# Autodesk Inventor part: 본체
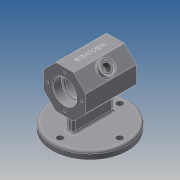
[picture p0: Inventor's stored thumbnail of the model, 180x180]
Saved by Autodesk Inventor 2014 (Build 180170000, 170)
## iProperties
Created: 2021-02
Part Number: 본체
Material: Generic
Document SubType Name: Modeling
Designer: kb542-20
Density: 1 g/cm^3
Appearance: Default
Author: kb542-20
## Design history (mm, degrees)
sketch "스케치1" dims "d0" = 58
  geometry: L1 (12.012, 29)-(29, 12.012); L2 (29, 12.012)-(29, -12.012); L3 (29, -12.012)-(12.012, -29); L4 (12.012, -29)-(-12.012, -29); L5 (-12.012, -29)-(-29, -12.012); L6 (-29, -12.012)-(-29, 12.012); L7 (-29, 12.012)-(-12.012, 29); L8 (-12.012, 29)-(12.012, 29); 5 further points
  constraints: 16 end point, 3 coincident, 1 horizontal, 1 midpoint, 1 vertical alignment, 19 other
extrude "돌출1" new body sketch "스케치1" stored distance "d1" = 70; taper "d2" = 0 deg
node "작업 평면1"
sketch "스케치3"
  geometry: C1 r 52 at (0, 0); C2 r 4.5 at (0, 41); C3 r 4.5 at (-41, 0); C4 r 4.5 at (0, -41); C5 r 4.5 at (41, 0); A1 r 41 centre (0, 0) between (0, 41) and (-41, 0); 1 further point
  constraints: 6 centre point, 4 point on circle, 3 equal radius, 2 coincident, 2 horizontal alignment, 2 vertical alignment
  dimensions: "d14" = 104 diameter of C1; "d15" = 82 diameter of A1; "d16" = 9 diameter of C2
extrude "돌출2" join sketch "스케치3" distance "d17" = 10; taper "d18" = 0 deg
sketch "스케치4"
  geometry: L1 (-5, 28)-(5, 28); L2 (5, 28)-(5, -28); L3 (5, -28)-(-5, -28); L4 (-5, -28)-(-5, 28); C1 r 52 at (0, 0) reference; 2 further points
  constraints: 8 end point, 2 midpoint, 2 parallel, 1 horizontal, 1 horizontal alignment, 1 perpendicular, 1 vertical alignment
  dimensions: "d19" = 56 distance of L1.end L2.end; "d20" = 10 distance of L1.start L1.end
extrude "돌출3" join sketch "스케치4" stored distance "d21" = 10; taper "d22" = 0 deg
sketch "스케치7"
  geometry: L1 (-35, 12.012)-(-35, -12.012) reference; L2 (-35, 0)-(0, 0); L3 (-35, 0)-(-35, 16); L4 (-35, 16)-(-23, 16); L5 (-23, 16)-(-23, 14); L6 (-23, 14)-(-20, 14); L7 (-20, 14)-(-20, 22); L8 (-20, 22)-(0, 22); L9 (0, 22)-(0, 0); L10 (35, 0)-(0, 0); L11 (35, 0)-(35, 16); L12 (35, 16)-(23, 16); L13 (23, 16)-(23, 14); L14 (23, 14)-(20, 14); L15 (20, 14)-(20, 22); L16 (20, 22)-(0, 22); 1 further point
  constraints: 30 end point, 7 symmetric about line, 5 parallel, 2 perpendicular, 1 midpoint
  dimensions: "d39" = 44 diameter of L16 L10; "d40" = 32 diameter of L4 L2; "d41" = 28 diameter of L6 L2; "d42" = 12 distance of L3.end L4.end; "d43" = 3 distance of L5.end L6.end
revolve "회전2" sketch "스케치7" stored, may be unused: angle "d44" = 90 deg
sketch "스케치8"
  geometry: L1 (-24.024, 70)-(0, 70) reference; L2 (-41.012, 0)-(-41.012, 70) reference; C1 r 10 at (-12.012, 35); 1 further point
  constraints: 1 centre point, 1 coincident
  dimensions: "d45" = 29 distance from line of L2 C1.centre (derived); "d46" = 35 distance from line of L1 point (-12.012, 35) (derived); "d47" = 20 diameter of C1
extrude "돌출5" join sketch "스케치8" distance "d48" = 5; taper "d49" = 0 deg
hole "구멍2" diameter "d52" = 10.917; stored, may be unused: countersink angle "d56" = 90 deg, drill point angle "d58" = 118 deg; dims "d50" = 10, "d51" = 10, "d53" = 6, "d54" = 16, "d55" = 2, "d57" = 8
sketch "스케치9"
  geometry: 2 further points
  constraints: 1 coincident, 1 other
feature "엠보싱2" sketch "스케치9" dims "d59" = 0.5, "d60" = 0
fillet "모깎기1" dims "d61" = 3, "d62" = 1
fillet "모깎기2" dims "d63" = 3, "d64" = 0.3
sketch "스케치10" dims "d65" = 46
  geometry: C1 r 16 at (0, 0) reference; 2 further points
  constraints: 2 vertical alignment, 1 coincident, 2 other
hole "구멍4" sketch "스케치10" at (0, 23) diameter "d73" = 3.242; stored, may be unused: countersink angle "d77" = 90 deg, drill point angle "d79" = 118 deg; dims "d74" = 8, "d75" = 16, "d76" = 2, "d78" = 10
chamfer "모따기1" distance "d83" = 1; stored, may be unused: second distance "d84" = 2, angle "d85" = 45 deg
node "솔리드1"
pattern_circular "원형 패턴1" dims angle "d81" = 360 deg
mirror "대칭1"
other parameters: "d13" = -62
